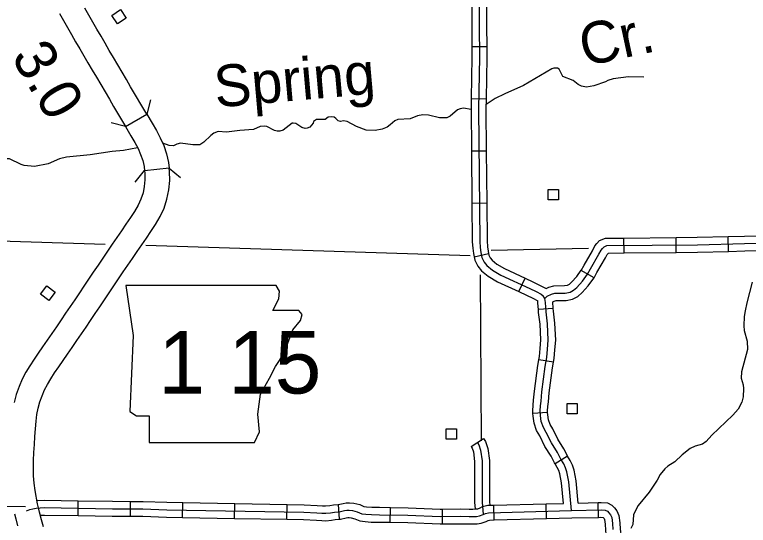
# Model space of a CAD drawing. Extents: x 1369885 to 1370219, y 379980 to 380218.
# Drawn here: x 1370050.18 to 1370079.7, y 380074 to 380094.55 of the extents above; entities that cross this region are included whole.
import ezdxf

# ---------------------------------------------------------------- set-up
doc = ezdxf.new("R2010")
doc.units = 0
for name, color, linetype in [('Level 10', 7, 'Continuous'), ('Level 21', 7, 'Continuous'), ('Level 32', 7, 'Continuous'), ('Level 35', 7, 'Continuous'), ('Level 37', 7, 'Continuous'), ('Level 4', 7, 'Continuous'), ('Level 45', 7, 'Continuous'), ('Level 48', 7, 'Continuous'), ('Level 5', 7, 'Continuous'), ('Level 56', 7, 'Continuous')]:
    doc.layers.add(name, color=color, linetype=linetype)

msp = doc.modelspace()

# ---------------------------------------------------------------- linework, layer by layer
at = {"layer": 'Level 10'}
for points in [[(1370054.637, 380090.045), (1370055.491, 380090.551), (1370054.844, 380091.652), (1370054.67, 380091.947), (1370054.498, 380092.242), (1370054.325, 380092.535), (1370054.154, 380092.826), (1370053.984, 380093.115), (1370053.816, 380093.4), (1370053.651, 380093.683), (1370053.486, 380093.965), (1370053.323, 380094.246), (1370053.161, 380094.528), (1370052.999, 380094.812)], [(1370051.974, 380094.597), (1370052.137, 380094.316), (1370052.298, 380094.034), (1370052.461, 380093.749), (1370052.627, 380093.464), (1370052.792, 380093.182), (1370052.958, 380092.898), (1370053.127, 380092.611), (1370053.297, 380092.322), (1370053.468, 380092.031), (1370053.64, 380091.738), (1370053.813, 380091.444), (1370053.986, 380091.149), (1370054.159, 380090.853), (1370054.637, 380090.045)], [(1370055.491, 380090.551), (1370055.713, 380090.18), (1370055.88, 380089.89), (1370056.036, 380089.596), (1370056.173, 380089.285), (1370056.285, 380088.954), (1370056.365, 380088.604), (1370056.392, 380088.375)], [(1370054.637, 380090.045), (1370054.853, 380089.681), (1370055.009, 380089.409), (1370055.141, 380089.161), (1370055.245, 380088.924), (1370055.327, 380088.683), (1370055.384, 380088.435), (1370055.403, 380088.267)], [(1370056.392, 380088.375), (1370055.403, 380088.267), (1370055.414, 380088.176), (1370055.418, 380087.909), (1370055.394, 380087.641), (1370055.341, 380087.381), (1370055.259, 380087.129), (1370055.146, 380086.88), (1370055.005, 380086.635), (1370054.833, 380086.385), (1370054.651, 380086.115), (1370054.471, 380085.847), (1370054.288, 380085.58), (1370054.1, 380085.309), (1370053.911, 380085.034), (1370053.721, 380084.756), (1370053.53, 380084.474), (1370053.341, 380084.191), (1370053.153, 380083.909), (1370052.965, 380083.629), (1370052.78, 380083.352), (1370052.596, 380083.08), (1370052.411, 380082.809), (1370052.226, 380082.538), (1370052.041, 380082.266), (1370051.854, 380081.993), (1370051.669, 380081.722), (1370051.482, 380081.454), (1370051.302, 380081.189), (1370051.128, 380080.934), (1370050.956, 380080.681), (1370050.79, 380080.424), (1370050.632, 380080.16), (1370050.484, 380079.88), (1370050.353, 380079.582), (1370050.241, 380079.27), (1370050.151, 380078.948)], [(1370051.337, 380073.934), (1370051.26, 380074.228), (1370051.182, 380074.528), (1370051.131, 380074.707), (1370051.095, 380074.866), (1370050.996, 380075.397), (1370050.957, 380075.691), (1370050.934, 380075.986), (1370050.931, 380076.29), (1370050.939, 380076.608), (1370050.953, 380076.931), (1370050.972, 380077.256), (1370050.99, 380077.578), (1370051.01, 380077.89), (1370051.035, 380078.186), (1370051.068, 380078.46), (1370051.119, 380078.717), (1370051.189, 380078.968), (1370051.277, 380079.213), (1370051.38, 380079.447), (1370051.499, 380079.673), (1370051.634, 380079.899), (1370051.785, 380080.132), (1370051.95, 380080.375), (1370052.124, 380080.629), (1370052.301, 380080.89), (1370052.487, 380081.157), (1370052.675, 380081.432), (1370052.862, 380081.705), (1370053.048, 380081.977), (1370053.233, 380082.249), (1370053.418, 380082.521), (1370053.605, 380082.796), (1370053.792, 380083.076), (1370053.979, 380083.356), (1370054.168, 380083.639), (1370054.355, 380083.92), (1370054.543, 380084.197), (1370054.731, 380084.472), (1370054.919, 380084.744), (1370055.107, 380085.016), (1370055.293, 380085.289), (1370055.476, 380085.56), (1370055.655, 380085.825), (1370055.847, 380086.105), (1370056.031, 380086.426), (1370056.187, 380086.766), (1370056.305, 380087.126), (1370056.38, 380087.497), (1370056.414, 380087.871), (1370056.408, 380088.241), (1370056.392, 380088.375)], [(1370050.168, 380074.458), (1370050.222, 380074.268), (1370050.297, 380073.978)]]:
    msp.add_lwpolyline(points, dxfattribs=at)
at = {"layer": 'Level 21'}
msp.add_lwpolyline([(1370054.644, 380083.658), (1370054.947, 380081.639), (1370054.813, 380078.577), (1370055.082, 380078.408), (1370055.586, 380078.408), (1370055.586, 380077.332), (1370059.826, 380077.332), (1370060.028, 380077.769), (1370059.961, 380078.476), (1370060.062, 380079.283), (1370060.432, 380079.923), (1370060.667, 380080.394), (1370061.004, 380080.898), (1370061.206, 380081.437), (1370061.374, 380081.874), (1370061.677, 380082.244), (1370061.744, 380082.48), (1370061.61, 380082.648), (1370060.566, 380082.648), (1370060.802, 380083.119), (1370060.836, 380083.422), (1370060.696, 380083.655)], close=True, dxfattribs=at)
at = {"layer": 'Level 32'}
for p, q in [((1370068.575, 380093.27), (1370069.172, 380093.273)), ((1370068.55, 380091.177), (1370069.147, 380091.167)), ((1370068.558, 380089.069), (1370069.155, 380089.074)), ((1370068.576, 380086.969), (1370069.173, 380086.974)), ((1370074.7, 380084.965), (1370074.694, 380085.562)), ((1370076.8, 380084.986), (1370076.794, 380085.582)), ((1370078.905, 380085.027), (1370078.889, 380085.623)), ((1370068.664, 380084.809), (1370069.246, 380084.942)), ((1370073.493, 380083.967), (1370072.971, 380084.256)), ((1370070.462, 380083.405), (1370070.712, 380083.947)), ((1370071.846, 380082.723), (1370071.251, 380082.68)), ((1370071.858, 380080.562), (1370071.27, 380080.66)), ((1370071.623, 380078.546), (1370071.028, 380078.506)), ((1370072.428, 380076.785), (1370071.92, 380076.474)), ((1370052.729, 380074.393), (1370052.738, 380074.99)), ((1370054.832, 380074.367), (1370054.836, 380074.964)), ((1370056.928, 380074.319), (1370056.939, 380074.915)), ((1370059.028, 380074.282), (1370059.039, 380074.878)), ((1370071.576, 380074.27), (1370071.561, 380074.866)), ((1370073.675, 380074.321), (1370073.661, 380074.917)), ((1370061.128, 380074.244), (1370061.139, 380074.841)), ((1370063.249, 380074.242), (1370063.209, 380074.837)), ((1370065.291, 380074.122), (1370065.3, 380074.719)), ((1370067.397, 380074.06), (1370067.393, 380074.657)), ((1370069.476, 380074.217), (1370069.461, 380074.813))]:
    msp.add_line(p, q, dxfattribs=at)
for points in [[(1370068.857, 380098.493), (1370068.869, 380094.084), (1370068.875, 380092.835), (1370068.842, 380090.758), (1370068.888, 380085.428), (1370068.912, 380085.179), (1370068.93, 380084.985), (1370068.978, 380084.773), (1370069.063, 380084.597), (1370069.178, 380084.46), (1370069.403, 380084.272), (1370069.742, 380084.066), (1370070.9, 380083.532), (1370071.162, 380083.404), (1370071.361, 380083.302), (1370071.439, 380083.241)], [(1370068.567, 380095.371), (1370068.571, 380094.083), (1370068.575, 380093.27)], [(1370069.164, 380095.373), (1370069.168, 380094.086), (1370069.172, 380093.273)], [(1370068.575, 380093.27), (1370068.577, 380092.837), (1370068.55, 380091.177)], [(1370069.172, 380093.273), (1370069.174, 380092.833), (1370069.147, 380091.167)], [(1370068.55, 380091.177), (1370068.544, 380090.759), (1370068.558, 380089.069)], [(1370069.147, 380091.167), (1370069.14, 380090.757), (1370069.155, 380089.074)], [(1370068.558, 380089.069), (1370068.576, 380086.969)], [(1370069.155, 380089.074), (1370069.173, 380086.974)], [(1370068.576, 380086.969), (1370068.589, 380085.412), (1370068.615, 380085.151), (1370068.635, 380084.938), (1370068.664, 380084.809)], [(1370069.173, 380086.974), (1370069.186, 380085.443), (1370069.209, 380085.207), (1370069.225, 380085.032), (1370069.246, 380084.942)], [(1370071.512, 380083.132), (1370071.609, 380083.223), (1370071.777, 380083.299), (1370071.915, 380083.339), (1370072.33, 380083.35), (1370072.524, 380083.387), (1370072.67, 380083.46), (1370072.797, 380083.575), (1370073.027, 380083.829), (1370073.227, 380084.102), (1370073.347, 380084.319), (1370073.688, 380084.909), (1370073.773, 380085.075), (1370073.833, 380085.142), (1370073.894, 380085.214), (1370074.009, 380085.257), (1370077.649, 380085.292), (1370079.547, 380085.342), (1370080.601, 380085.36), (1370083.893, 380085.451), (1370089.208, 380085.459), (1370094.485, 380085.583), (1370098.368, 380085.616), (1370099.652, 380085.622)], [(1370072.971, 380084.256), (1370073.088, 380084.466), (1370073.426, 380085.052), (1370073.525, 380085.246), (1370073.608, 380085.337), (1370073.716, 380085.467), (1370073.955, 380085.555), (1370074.694, 380085.562)], [(1370074.694, 380085.562), (1370076.794, 380085.582)], [(1370076.794, 380085.582), (1370077.643, 380085.591), (1370078.889, 380085.623)], [(1370078.889, 380085.623), (1370079.54, 380085.64), (1370080.595, 380085.658), (1370080.989, 380085.669)], [(1370069.246, 380084.942), (1370069.262, 380084.872), (1370069.316, 380084.76), (1370069.39, 380084.672), (1370069.577, 380084.515), (1370069.883, 380084.33), (1370070.712, 380083.947)], [(1370073.493, 380083.967), (1370073.607, 380084.173), (1370073.95, 380084.766), (1370074.02, 380084.904), (1370074.059, 380084.946), (1370074.07, 380084.959), (1370074.7, 380084.965)], [(1370074.7, 380084.965), (1370076.8, 380084.986)], [(1370076.8, 380084.986), (1370077.654, 380084.994), (1370078.905, 380085.027)], [(1370078.905, 380085.027), (1370079.553, 380085.043), (1370080.608, 380085.062), (1370081.005, 380085.073)], [(1370068.664, 380084.809), (1370068.695, 380084.673), (1370068.811, 380084.433), (1370068.967, 380084.248), (1370069.228, 380084.029), (1370069.602, 380083.802), (1370070.462, 380083.405)], [(1370071.567, 380083.531), (1370071.674, 380083.58), (1370071.869, 380083.636), (1370072.299, 380083.648), (1370072.428, 380083.672), (1370072.5, 380083.708), (1370072.586, 380083.786), (1370072.796, 380084.018), (1370072.975, 380084.263), (1370072.971, 380084.256)], [(1370070.712, 380083.947), (1370071.028, 380083.802), (1370071.296, 380083.671), (1370071.567, 380083.531)], [(1370071.827, 380082.994), (1370071.881, 380083.018), (1370071.962, 380083.042), (1370072.362, 380083.053), (1370072.62, 380083.101), (1370072.84, 380083.211), (1370073.008, 380083.364), (1370073.259, 380083.641), (1370073.479, 380083.941), (1370073.493, 380083.967)], [(1370070.462, 380083.405), (1370070.772, 380083.263), (1370071.029, 380083.137), (1370071.222, 380083.038)], [(1370071.357, 380078.997), (1370071.393, 380079.367), (1370071.527, 380080.386), (1370071.587, 380080.752), (1370071.618, 380081.085), (1370071.648, 380081.455), (1370071.618, 380082.116), (1370071.557, 380082.589), (1370071.53, 380082.962), (1370071.512, 380083.132), (1370071.439, 380083.241)], [(1370071.251, 380082.68), (1370071.233, 380082.936), (1370071.222, 380083.038)], [(1370071.846, 380082.723), (1370071.827, 380082.994)], [(1370071.27, 380080.66), (1370071.291, 380080.789), (1370071.32, 380081.111), (1370071.349, 380081.46), (1370071.32, 380082.09), (1370071.26, 380082.56), (1370071.251, 380082.68)], [(1370071.858, 380080.562), (1370071.883, 380080.714), (1370071.915, 380081.059), (1370071.947, 380081.45), (1370071.915, 380082.142), (1370071.854, 380082.619), (1370071.846, 380082.723)], [(1370071.028, 380078.506), (1370071.022, 380078.602), (1370071.035, 380078.831), (1370071.06, 380079.031), (1370071.097, 380079.401), (1370071.231, 380080.43), (1370071.27, 380080.66)], [(1370071.623, 380078.546), (1370071.619, 380078.604), (1370071.63, 380078.776), (1370071.653, 380078.964), (1370071.69, 380079.333), (1370071.822, 380080.343), (1370071.858, 380080.562)], [(1370072.586, 380074.594), (1370072.471, 380075.752), (1370072.399, 380076.151), (1370072.344, 380076.313), (1370072.272, 380076.47), (1370072.157, 380076.657), (1370072.018, 380076.929), (1370071.776, 380077.322), (1370071.565, 380077.74), (1370071.454, 380077.936), (1370071.369, 380078.179), (1370071.333, 380078.421), (1370071.321, 380078.603), (1370071.333, 380078.803), (1370071.357, 380078.997)], [(1370071.92, 380076.474), (1370071.897, 380076.511), (1370071.758, 380076.783), (1370071.516, 380077.177), (1370071.302, 380077.599), (1370071.181, 380077.812), (1370071.078, 380078.107), (1370071.036, 380078.389), (1370071.028, 380078.506)], [(1370072.428, 380076.785), (1370072.417, 380076.803), (1370072.278, 380077.076), (1370072.037, 380077.468), (1370071.828, 380077.881), (1370071.727, 380078.06), (1370071.66, 380078.251), (1370071.63, 380078.453), (1370071.623, 380078.546)], [(1370072.856, 380074.899), (1370072.767, 380075.793), (1370072.688, 380076.225), (1370072.622, 380076.423), (1370072.535, 380076.611), (1370072.428, 380076.785)], [(1370072.257, 380074.884), (1370072.175, 380075.71), (1370072.109, 380076.076), (1370072.067, 380076.203), (1370072.008, 380076.329), (1370071.92, 380076.474)], [(1370051.071, 380074.995), (1370051.359, 380075.011), (1370052.738, 380074.99)], [(1370052.738, 380074.99), (1370054.111, 380074.969), (1370054.836, 380074.964)], [(1370054.836, 380074.964), (1370054.992, 380074.962), (1370055.341, 380074.959), (1370056.305, 380074.927), (1370056.939, 380074.915)], [(1370056.939, 380074.915), (1370059.039, 380074.878)], [(1370059.039, 380074.878), (1370061.139, 380074.841)], [(1370063.193, 380074.836), (1370063.39, 380074.885), (1370063.518, 380074.906), (1370063.645, 380074.911), (1370063.82, 380074.898), (1370064.06, 380074.833), (1370064.227, 380074.76), (1370064.339, 380074.747), (1370064.551, 380074.728), (1370064.861, 380074.725), (1370065.3, 380074.719)], [(1370069.461, 380074.813), (1370071.561, 380074.866)], [(1370071.561, 380074.866), (1370072.257, 380074.884)], [(1370072.856, 380074.899), (1370073.661, 380074.917)], [(1370073.661, 380074.917), (1370073.778, 380074.92), (1370074.027, 380074.905), (1370074.212, 380074.806), (1370074.313, 380074.706), (1370074.407, 380074.58), (1370074.492, 380074.4), (1370074.529, 380074.099), (1370074.544, 380073.852), (1370074.577, 380073.546), (1370074.614, 380073.092), (1370074.63, 380072.932)], [(1370046.869, 380074.808), (1370050.608, 380074.764)], [(1370050.65, 380074.583), (1370050.715, 380074.609), (1370050.793, 380074.632), (1370050.913, 380074.667), (1370051.037, 380074.687), (1370051.196, 380074.703), (1370051.365, 380074.713), (1370054.108, 380074.671), (1370054.989, 380074.664), (1370055.335, 380074.661), (1370056.297, 380074.628), (1370061.813, 380074.531), (1370062.335, 380074.501), (1370062.543, 380074.492), (1370062.693, 380074.485), (1370062.891, 380074.505), (1370063.044, 380074.527), (1370063.239, 380074.54), (1370063.45, 380074.592), (1370063.548, 380074.609), (1370063.639, 380074.612), (1370063.769, 380074.602), (1370063.961, 380074.55), (1370064.149, 380074.469), (1370064.308, 380074.45), (1370064.536, 380074.43), (1370064.857, 380074.427), (1370066, 380074.41), (1370067.297, 380074.358), (1370068.128, 380074.363), (1370068.462, 380074.357), (1370068.622, 380074.355), (1370068.755, 380074.361), (1370068.882, 380074.378), (1370069.028, 380074.43), (1370069.116, 380074.479), (1370069.249, 380074.509), (1370072.586, 380074.594), (1370073.773, 380074.621), (1370073.944, 380074.611), (1370074.033, 380074.564), (1370074.087, 380074.51), (1370074.15, 380074.425), (1370074.202, 380074.316), (1370074.232, 380074.071), (1370074.247, 380073.827)], [(1370061.139, 380074.841), (1370061.824, 380074.829), (1370062.351, 380074.799), (1370062.557, 380074.79), (1370062.685, 380074.784), (1370062.855, 380074.801), (1370063.012, 380074.824), (1370063.209, 380074.837)], [(1370065.3, 380074.719), (1370066.008, 380074.709), (1370067.302, 380074.657), (1370067.393, 380074.657)], [(1370067.393, 380074.657), (1370068.13, 380074.661), (1370068.467, 380074.655), (1370068.616, 380074.653), (1370068.729, 380074.659), (1370068.812, 380074.67), (1370068.905, 380074.703), (1370069.008, 380074.76), (1370069.211, 380074.807), (1370069.461, 380074.813)], [(1370051.214, 380074.405), (1370051.371, 380074.414), (1370052.729, 380074.393)], [(1370052.729, 380074.393), (1370054.104, 380074.372), (1370054.832, 380074.367)], [(1370054.832, 380074.367), (1370054.986, 380074.366), (1370055.329, 380074.363), (1370056.29, 380074.33), (1370056.928, 380074.319)], [(1370056.928, 380074.319), (1370059.028, 380074.282)], [(1370059.028, 380074.282), (1370061.128, 380074.244)], [(1370063.249, 380074.242), (1370063.285, 380074.244), (1370063.511, 380074.3), (1370063.578, 380074.311), (1370063.633, 380074.313), (1370063.718, 380074.307), (1370063.862, 380074.268), (1370064.07, 380074.178), (1370064.277, 380074.153), (1370064.522, 380074.132), (1370064.854, 380074.129), (1370065.291, 380074.122)], [(1370069.476, 380074.217), (1370071.576, 380074.27)], [(1370071.576, 380074.27), (1370072.593, 380074.296), (1370073.675, 380074.321)], [(1370073.675, 380074.321), (1370073.767, 380074.323), (1370073.857, 380074.318), (1370073.861, 380074.314), (1370073.894, 380074.27), (1370073.912, 380074.232), (1370073.935, 380074.044), (1370073.95, 380073.801), (1370073.983, 380073.49), (1370074.019, 380073.038), (1370074.036, 380072.872)], [(1370061.128, 380074.244), (1370061.802, 380074.232), (1370062.32, 380074.203), (1370062.53, 380074.194), (1370062.701, 380074.186), (1370062.928, 380074.208), (1370063.076, 380074.231), (1370063.249, 380074.242)], [(1370065.291, 380074.122), (1370065.991, 380074.112), (1370067.292, 380074.06), (1370067.397, 380074.06)], [(1370067.397, 380074.06), (1370068.126, 380074.064), (1370068.458, 380074.059), (1370068.627, 380074.057), (1370068.781, 380074.064), (1370068.951, 380074.086), (1370069.151, 380074.157), (1370069.224, 380074.197), (1370069.287, 380074.212), (1370069.476, 380074.217)]]:
    msp.add_lwpolyline(points, dxfattribs=at)
at = {"layer": 'Level 35'}
for points in [[(1370075.488, 380092.038), (1370074.872, 380092.047), (1370074.263, 380091.973), (1370074.05, 380091.906), (1370073.949, 380091.852), (1370073.481, 380091.682), (1370073.185, 380091.633), (1370072.985, 380091.675), (1370072.856, 380091.735), (1370072.648, 380091.9), (1370072.238, 380092.067), (1370072.082, 380092.353), (1370072.017, 380092.395), (1370071.866, 380092.398), (1370071.788, 380092.368), (1370070.648, 380091.707), (1370069.9, 380091.366), (1370069.516, 380091.171), (1370069.143, 380090.933)], [(1370068.544, 380090.738), (1370068.241, 380090.785), (1370068.099, 380090.765), (1370068.001, 380090.726), (1370067.702, 380090.47), (1370067.562, 380090.398), (1370067.275, 380090.405), (1370066.835, 380090.511), (1370066.605, 380090.516), (1370066.391, 380090.474), (1370066.093, 380090.353), (1370065.589, 380090.33), (1370065.468, 380090.283), (1370065.29, 380090.114), (1370065.162, 380090.022), (1370064.958, 380089.94), (1370064.677, 380089.884), (1370064.315, 380089.909), (1370063.938, 380090.049), (1370063.554, 380090.252), (1370063.406, 380090.28), (1370063.284, 380090.256), (1370063.196, 380090.273), (1370063.105, 380090.374), (1370063.029, 380090.42), (1370062.936, 380090.445), (1370062.786, 380090.428), (1370062.67, 380090.337), (1370062.316, 380090.338), (1370062.203, 380090.251), (1370062.182, 380090.187)], [(1370062.182, 380090.187), (1370062.055, 380090.027), (1370061.953, 380089.981), (1370061.862, 380089.97), (1370061.73, 380090.01), (1370061.495, 380090.17), (1370061.387, 380090.191), (1370061.344, 380090.181), (1370060.987, 380089.903), (1370060.841, 380089.859), (1370060.742, 380089.86), (1370060.637, 380089.889), (1370060.323, 380090.047), (1370060.223, 380090.064), (1370060.057, 380090.047), (1370059.782, 380089.931), (1370059.235, 380089.894), (1370058.701, 380089.826), (1370058.367, 380089.844), (1370058.19, 380089.783), (1370058.065, 380089.691), (1370057.792, 380089.416), (1370057.624, 380089.315), (1370057.346, 380089.307), (1370056.851, 380089.383), (1370056.702, 380089.343), (1370056.565, 380089.271), (1370056.39, 380089.285), (1370056.142, 380089.377)], [(1370055.125, 380089.196), (1370054.552, 380089.09), (1370054.101, 380089.045), (1370053.215, 380088.906), (1370052.257, 380088.813), (1370051.977, 380088.745), (1370051.522, 380088.548), (1370050.977, 380088.447), (1370050.563, 380088.483), (1370050.442, 380088.519), (1370049.963, 380088.751), (1370049.804, 380088.751), (1370049.456, 380088.684), (1370049.029, 380088.504)], [(1370079.858, 380083.78), (1370079.637, 380082.956), (1370079.571, 380082.639), (1370079.535, 380082.399), (1370079.518, 380082.035), (1370079.532, 380081.836), (1370079.656, 380081.406), (1370079.67, 380081.083), (1370079.424, 380080.171), (1370079.411, 380079.923), (1370079.487, 380079.659), (1370079.504, 380079.504), (1370079.49, 380079.176), (1370079.437, 380078.959), (1370079.29, 380078.68), (1370079.071, 380078.434), (1370078.226, 380077.627), (1370078.003, 380077.373), (1370077.848, 380077.269), (1370077.564, 380077.185), (1370077.353, 380077.086), (1370077.038, 380076.842), (1370076.737, 380076.55), (1370076.46, 380076.382), (1370076.332, 380076.278), (1370076.153, 380076.045), (1370076.032, 380075.823), (1370075.702, 380075.33), (1370075.265, 380074.799), (1370075.141, 380074.576), (1370075.082, 380074.419), (1370075.046, 380074.039), (1370074.972, 380073.873)]]:
    msp.add_lwpolyline(points, dxfattribs=at)
at = {"layer": 'Level 37'}
for points in [[(1370055.64, 380091.13), (1370055.492, 380090.552)], [(1370054.636, 380090.045), (1370054.058, 380090.193)], [(1370055.025, 380087.813), (1370055.403, 380088.275)], [(1370056.392, 380088.375), (1370056.854, 380087.998)]]:
    msp.add_lwpolyline(points, dxfattribs=at)
at = {"layer": 'Level 4'}
msp.add_lwpolyline([(1370068.908, 380084.085), (1370068.947, 380077.402)], dxfattribs=at)
at = {"layer": 'Level 45'}
msp.add_line((1370068.542, 380077.177), (1370069.046, 380077.496), dxfattribs=at)
for points in [[(1370068.794, 380077.337), (1370068.856, 380077.239), (1370068.927, 380077.028), (1370068.982, 380076.59), (1370068.982, 380074.928), (1370069.028, 380074.43)], [(1370069.046, 380077.496), (1370069.127, 380077.369), (1370069.219, 380077.095), (1370069.281, 380076.609), (1370069.281, 380075.27)], [(1370068.542, 380077.177), (1370068.584, 380077.11), (1370068.635, 380076.96), (1370068.684, 380076.571), (1370068.684, 380075.27)], [(1370068.684, 380075.27), (1370068.684, 380074.914), (1370068.707, 380074.658)], [(1370069.281, 380075.27), (1370069.281, 380074.941), (1370069.293, 380074.809)]]:
    msp.add_lwpolyline(points, dxfattribs=at)
at = {"layer": 'Level 5'}
for points in [[(1370047.851, 380085.507), (1370053.821, 380085.32)], [(1370055.457, 380085.269), (1370068.508, 380084.862)], [(1370069.347, 380085.076), (1370073.27, 380085.149)]]:
    msp.add_lwpolyline(points, dxfattribs=at)
at = {"layer": 'Level 56'}
for points in [[(1370054.318, 380094.179), (1370054.085, 380094.521), (1370054.429, 380094.754), (1370054.661, 380094.412)], [(1370071.65, 380087.095), (1370071.65, 380087.509), (1370072.065, 380087.509), (1370072.065, 380087.095)], [(1370051.222, 380083.309), (1370051.475, 380083.637), (1370051.804, 380083.383), (1370051.551, 380083.055)], [(1370072.402, 380078.483), (1370072.402, 380078.897), (1370072.817, 380078.897), (1370072.817, 380078.483)], [(1370067.543, 380077.471), (1370067.543, 380077.886), (1370067.958, 380077.886), (1370067.958, 380077.471)]]:
    msp.add_lwpolyline(points, close=True, dxfattribs=at)

# ---------------------------------------------------------------- texts
at = {"layer": 'Level 21'}
msp.add_text('1 15', height=2.5204, dxfattribs=at).set_placement((1370055.958, 380079.305))
at = {"layer": 'Level 35'}
for s, rotation, p in [('Cr.', 12.0806, (1370073.099, 380092.461)), ('Spring', 5.0073, (1370058.271, 380090.813))]:
    msp.add_text(s, height=1.6802, rotation=rotation, dxfattribs=at).set_placement(p)
at = {"layer": 'Level 48'}
msp.add_text('3.0', height=1.6802, rotation=300.5607, dxfattribs=at).set_placement((1370050.01, 380092.865))

doc.saveas('drawing.dxf')
